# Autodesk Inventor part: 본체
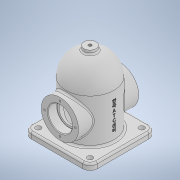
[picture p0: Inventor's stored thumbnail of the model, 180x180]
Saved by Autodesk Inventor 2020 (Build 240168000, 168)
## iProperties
Created: 2021-07
Part Number: 본체
Material: 일반
Document SubType Name: Modeling
Designer: Owner
Density: 1 g/cm^3
Appearance: 기본값
Author: Owner
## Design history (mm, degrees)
sketch "스케치1"
  geometry: C1 r 40 at (0, 0); 1 further point
  constraints: 1 centre point, 1 coincident
  dimensions: "d0" = 80 diameter of C1
extrude "돌출1" new body sketch "스케치1" distance "d1" = 124; taper "d2" = 0 deg
fillet "모깎기1" dims "d3" = 40
feature "쉘1" dims "d4" = 8
node "작업 평면1"
sketch "스케치2"
  geometry: C1 r 31 at (0, 48); 1 further point
  constraints: 1 centre point, 1 vertical alignment
  dimensions: "d6" = 62 diameter of C1; "d7" = 48 distance of point (0, 0) C1.centre
extrude "돌출2" join sketch "스케치2" stored distance "d8" = 124; taper "d9" = 0 deg
sketch "스케치3" dims "d10" = 51
  geometry: 3 further points
  constraints: 2 vertical alignment, 2 other
  dimensions: "d11" = 48 distance of point (0, -48) point (0, 0)
hole "구멍1" sketch "스케치3" at (0, 25.5) diameter "d12" = 3.242; stored, may be unused: countersink angle "d16" = 90 deg, drill point angle "d18" = 118 deg; dims "d13" = 8, "d14" = 4, "d15" = 2, "d17" = 10
sketch "스케치4"
  geometry: C1 r 31 at (0, 0) reference; 2 further points
  constraints: 1 coincident
hole "구멍2" sketch "스케치4" at (0, 0) diameter "d22" = 33; stored, may be unused: countersink angle "d26" = 90 deg, drill point angle "d28" = 118 deg; dims "d23" = 8, "d24" = 40, "d25" = 15, "d27" = 10
chamfer "모따기1" distance "d29" = 1; stored, may be unused: second distance "d30" = 2, angle "d31" = 45 deg
fillet "모깎기2" dims "d32" = 0.3
fillet "모깎기3" dims "d33" = 3
node "작업 평면2"
sketch "스케치5"
  geometry: 2 further points
  constraints: 1 horizontal alignment, 1 other
  dimensions: "d35" = 48 distance of point (0, 0) point (48, 0)
feature "엠보싱1" sketch "스케치5" dims "d36" = 0.5, "d37" = 0
node "작업 평면3"
sketch "스케치6"
  geometry: C1 r 10 at (0, 0); 1 further point
  constraints: 1 centre point, 1 coincident
  dimensions: "d39" = 20 diameter of C1
extrude "돌출3" join sketch "스케치6" stored distance "d40" = 124; taper "d41" = 0 deg
sketch "스케치7"
  geometry: C1 r 10 at (0, 0) reference; 2 further points
  constraints: 1 coincident
hole "구멍3" sketch "스케치7" at (0, 0) diameter "d42" = 5.1881; stored, may be unused: countersink angle "d46" = 90 deg, drill point angle "d48" = 118 deg; dims "d43" = 15, "d44" = 4, "d45" = 2, "d47" = 16
fillet "모깎기4" dims "d49" = 3
sketch "스케치8"
  geometry: L1 (55, 55)-(-55, 55); L2 (-55, 55)-(-55, -55); L3 (-55, -55)-(55, -55); L4 (55, -55)-(55, 55); L5 (55, 55)-(-55, -55); L6 (-55, 55)-(55, -55); C1 r 32 at (0, 0) reference; C2 r 40 at (0, 0) reference; 1 further point
  constraints: 12 end point, 2 midpoint, 2 parallel, 1 horizontal, 1 perpendicular
  dimensions: "d50" = 110 distance of L3.end L2.end; "d51" = 110 distance of L2.end L1.end
extrude "돌출4" join sketch "스케치8" distance "d52" = 10; taper "d53" = 0 deg
fillet "모깎기5" dims "d54" = 12
fillet "모깎기6" dims "d55" = 3
sketch "스케치9"
  geometry: A1 r 9 centre (-43, -43) between (-52, -43) and (-43, -52) reference; 2 further points
  constraints: 1 coincident
hole "구멍4" sketch "스케치9" at (-43, -43) diameter "d56" = 9; stored, may be unused: countersink angle "d60" = 90 deg, drill point angle "d62" = 0 deg; dims "d57" = 15, "d58" = 4, "d59" = 2, "d61" = 10
fillet "모깎기7" dims "d66" = 3
node "솔리드1"
pattern_circular "원형 패턴1" dims angle "d20" = 360 deg
mirror "미러1"
pattern_circular "원형 패턴2" dims angle "d64" = 360 deg
feature "A9D066F2-1C7D-4E18-AEED-F7BC21143FA4" dims "d22" = 33, "d23" = 8, "d24" = 40, "d25" = 15, "d26" = 90 deg, "d27" = 10, "d28" = 118 deg
other parameters: "d38" = 129
